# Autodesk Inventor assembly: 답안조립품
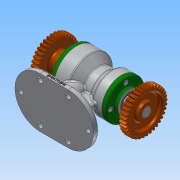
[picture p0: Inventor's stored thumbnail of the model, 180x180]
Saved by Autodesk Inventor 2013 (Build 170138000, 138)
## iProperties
Created: 2020-01
Part Number: 답안조립품
Document SubType Name: Assembly
Designer: Administrator
Author: Administrator
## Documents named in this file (13)
- C:\Users\Administrator\Desktop\700104V1016\답안조립품.iam
- C:\Users\Administrator\Desktop\700104V1016\본체.ipt
- C:\Users\Administrator\Desktop\700104V1016\뒤커버.ipt
- C:\Users\Administrator\Desktop\700104V1016\멈춤나사 M3.ipt
- C:\Users\Administrator\Desktop\700104V1016\베어링 6203.ipt
- C:\Users\Administrator\Desktop\700104V1016\베어링 6205.ipt
- C:\Users\Administrator\Desktop\700104V1016\볼트 M4.ipt
- C:\Users\Administrator\Desktop\700104V1016\스퍼기어.ipt
- C:\Users\Administrator\Desktop\700104V1016\앞커버.ipt
- C:\Users\Administrator\Desktop\700104V1016\오일 실 17 30 8.ipt
- C:\Users\Administrator\Desktop\700104V1016\오일 실 25 38 8.ipt
- C:\Users\Administrator\Desktop\700104V1016\축.ipt
- C:\Users\Administrator\Desktop\700104V1016\키 5 x 5 x 18.ipt
